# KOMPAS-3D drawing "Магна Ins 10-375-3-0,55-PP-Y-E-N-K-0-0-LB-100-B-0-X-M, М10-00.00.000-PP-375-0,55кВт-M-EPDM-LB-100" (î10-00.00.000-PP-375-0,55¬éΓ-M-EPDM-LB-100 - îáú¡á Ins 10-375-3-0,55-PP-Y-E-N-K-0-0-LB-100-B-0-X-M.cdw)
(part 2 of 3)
- Part/product: Магна Ins 10-425-3-0,75-PP-Y-E-N-K-0-0-L-0-B-0-X-M  | designation М10-00.00.000-PP-425-0,75кВт-M-EPDM
    Масса: 15.988
  - Component [detail]: Заглушка @2~25 FV PPR ф. "FV-Plast"  | qty 4  | pos. 12  | Материал: Полипропилен  ГОСТ 26996-86 (density 900 kg/m3); Масса: 0.0161976; Раздел спецификации: Прочие изделия
  - Component [standard]: Болт М10-6gx60.21.12Х18Н10Т ГОСТ 7798-70  | qty 4  | pos. 8  | Масса: 0.0467; Раздел спецификации: Стандартные изделия; additional columns: М8-6gx55.21.12Х18Н10Т; Сталь 12Х18Н10Т ГОСТ 5632-72
  - Component [standard]: Гайка М10x1,25-6H(S16) ГОСТ 5915-70  | qty 4  | pos. 9  | Масса: 0.01022; Раздел спецификации: Стандартные изделия; Рассекать на разрезах: no; additional columns: М10x1,25-6H (S16); Сталь 12Х18Н10Т ГОСТ 5632-72
  - Component [standard]: Шайба 10 ГОСТ 6402-70  | qty 4  | pos. 10  | Масса: 0.00201; Раздел спецификации: Стандартные изделия; Примечание: Нерж.; Рассекать на разрезах: no; additional columns: 10; Без указания материала
  - Component [standard]: Шайба C.10.21 ГОСТ 11371-78  | qty 4  | pos. 11  | Материал: Сталь 12Х18Н10Т ГОСТ 5632-72 (density 1000 kg/m3); Масса: 0.003438; Раздел спецификации: Стандартные изделия; Рассекать на разрезах: no; additional columns: Сталь 12Х18Н10Т ГОСТ 5632-72
  - Component [standard]: Шайба C.10.21 ГОСТ 11371-78  | qty 4  | pos. 11  | Материал: Сталь 12Х18Н10Т ГОСТ 5632-72 (density 1000 kg/m3); Масса: 0.003438; Раздел спецификации: Стандартные изделия; additional columns: C.8.21; Сталь 12Х18Н10Т ГОСТ 5632-72
  - Component [detail]: Втулка ответная  | designation М10А-00.00.003-01  | pos. 6  | Масса: 0.031838; Раздел спецификации: Детали; Форматы листов документа: A4; Примечание: Заим.; source file: ..\..\..\..\..\..\AquaProf\АкваProf 190\3Д модель\М10А-00.00.003 - Втулка ответная.m3d, ..\М10А-00.00.003-01 - Втулка ответная.cdw
  - Component [detail]: Защитная втулка  | designation М10-00.00.003  | pos. 5  | Масса: 0.0193569; Раздел спецификации: Детали; Форматы листов документа: A4; source file: ..\М10-00.00.003 - Защитная втулка.cdw, ..\М10-00.00.003 - Защитная втулка.m3d
  - Component [detail]: Импеллер Магна10  | designation М10-00.00.001  | pos. 3  | Масса: 0.169927; Раздел спецификации: Детали; Форматы листов документа: A3; source file: ..\М10-00.00.001 - Импеллер Магна10.cdw, ..\М10-00.00.001 - Импеллер Магна10.m3d
  - Component [detail]: Крышка  | designation М10-00.00.002  | pos. 4
      Материал: Полипропилен  ГОСТ 26996-86 (density 900 kg/m3)
      Масса: 0.324102
      Раздел спецификации: Детали
      Форматы листов документа: 4xA4
      Примечание: @100~)4xA4
      source file: ..\М10-00.00.002 - Крышка.cdw, ..\М10-00.00.002 - Крышка.m3d
  - Component [assembly]: Вал  | designation М10-00.15.000-0,75кВт-425  | pos. 1
      Материал: Полипропилен  ГОСТ 26996-86 (density 900 kg/m3)
      Масса: 0.908797
      Раздел спецификации: Сборочные единицы
      Форматы листов документа: 2xA3
      Примечание: @100~)2xA3
      source file: ..\М10-00.15.000 - Вал.a3d
  - Component [assembly]: Корпус полипропилен 425 0,75кВт  / с разъёмной муфтой  | designation М10-00.20.000-PP-425-0,75кВт-M  | pos. 2  | Материал: Полипропилен  ГОСТ 26996-86 (density 900 kg/m3); Масса: 5.90542; Раздел спецификации: Сборочные единицы; Форматы листов документа: 3xA3; Примечание: @100~)3xA3@101~)3xA3
- Part/product: Магна Ins 10-425-3-0,75-PP-Y-E-N-K-0-0-L-0-B-0-X-R  | designation М10-00.00.000-PP-425-0,75кВт-R-EPDM
    Масса: 15.0715
  - Component [detail]: Заглушка @2~25 FV PPR ф. "FV-Plast"  | qty 4  | pos. 12  | Материал: Полипропилен  ГОСТ 26996-86 (density 900 kg/m3); Масса: 0.0161976; Раздел спецификации: Прочие изделия
  - Component [standard]: Болт М10-6gx60.21.12Х18Н10Т ГОСТ 7798-70  | qty 4  | pos. 8  | Масса: 0.0467; Раздел спецификации: Стандартные изделия; additional columns: М8-6gx55.21.12Х18Н10Т; Сталь 12Х18Н10Т ГОСТ 5632-72
  - Component [standard]: Гайка М10x1,25-6H(S16) ГОСТ 5915-70  | qty 4  | pos. 9  | Масса: 0.01022; Раздел спецификации: Стандартные изделия; Рассекать на разрезах: no; additional columns: М10x1,25-6H (S16); Сталь 12Х18Н10Т ГОСТ 5632-72
  - Component [standard]: Шайба 10 ГОСТ 6402-70  | qty 4  | pos. 10  | Масса: 0.00201; Раздел спецификации: Стандартные изделия; Примечание: Нерж.; Рассекать на разрезах: no; additional columns: 10; Без указания материала
  - Component [standard]: Шайба C.10.21 ГОСТ 11371-78  | qty 4  | pos. 11  | Материал: Сталь 12Х18Н10Т ГОСТ 5632-72 (density 1000 kg/m3); Масса: 0.003438; Раздел спецификации: Стандартные изделия; Рассекать на разрезах: no; additional columns: Сталь 12Х18Н10Т ГОСТ 5632-72
  - Component [standard]: Шайба C.10.21 ГОСТ 11371-78  | qty 4  | pos. 11  | Материал: Сталь 12Х18Н10Т ГОСТ 5632-72 (density 1000 kg/m3); Масса: 0.003438; Раздел спецификации: Стандартные изделия; additional columns: C.8.21; Сталь 12Х18Н10Т ГОСТ 5632-72
  - Component [detail]: Втулка ответная  | designation М10А-00.00.003-01  | pos. 6  | Масса: 0.031838; Раздел спецификации: Детали; Форматы листов документа: A4; Примечание: Заим.; source file: ..\..\..\..\..\..\AquaProf\АкваProf 190\3Д модель\М10А-00.00.003 - Втулка ответная.m3d, ..\М10А-00.00.003-01 - Втулка ответная.cdw
  - Component [detail]: Защитная втулка  | designation М10-00.00.003  | pos. 5  | Масса: 0.0193569; Раздел спецификации: Детали; Форматы листов документа: A4; source file: ..\М10-00.00.003 - Защитная втулка.cdw, ..\М10-00.00.003 - Защитная втулка.m3d
  - Component [detail]: Импеллер Магна10  | designation М10-00.00.001  | pos. 3  | Масса: 0.169927; Раздел спецификации: Детали; Форматы листов документа: A3; source file: ..\М10-00.00.001 - Импеллер Магна10.cdw, ..\М10-00.00.001 - Импеллер Магна10.m3d
  - Component [detail]: Крышка  | designation М10-00.00.002  | pos. 4
      Материал: Полипропилен  ГОСТ 26996-86 (density 900 kg/m3)
      Масса: 0.324102
      Раздел спецификации: Детали
      Форматы листов документа: 4xA4
      Примечание: @100~)4xA4
      source file: ..\М10-00.00.002 - Крышка.cdw, ..\М10-00.00.002 - Крышка.m3d
  - Component [assembly]: Вал  | designation М10-00.15.000-0,75кВт-425  | pos. 1
      Материал: Полипропилен  ГОСТ 26996-86 (density 900 kg/m3)
      Масса: 0.908797
      Раздел спецификации: Сборочные единицы
      Форматы листов документа: 2xA3
      Примечание: @100~)2xA3
      source file: ..\М10-00.15.000 - Вал.a3d
  - Component [assembly]: Корпус полипропилен 425 0,75кВт  / с резьбовым переходником  | designation М10-00.20.000-PP-425-0,75кВт-R  | pos. 2  | Материал: Полипропилен  ГОСТ 26996-86 (density 900 kg/m3); Масса: 4.98891; Раздел спецификации: Сборочные единицы; Форматы листов документа: 3xA3; Примечание: @100~)3xA3@101~)3xA3
- Part/product: Магна Ins 10-425-3-1,1-PP-Y-E-N-K-0-0-L-0-B-0-X-M  | designation М10-00.00.000-PP-425-1,1кВт-M-EPDM
    Масса: 15.9855
  - Component [detail]: Заглушка @2~25 FV PPR ф. "FV-Plast"  | qty 4  | pos. 12  | Материал: Полипропилен  ГОСТ 26996-86 (density 900 kg/m3); Масса: 0.0161976; Раздел спецификации: Прочие изделия
  - Component [standard]: Болт М10-6gx60.21.12Х18Н10Т ГОСТ 7798-70  | qty 4  | pos. 8  | Масса: 0.0467; Раздел спецификации: Стандартные изделия; additional columns: М8-6gx55.21.12Х18Н10Т; Сталь 12Х18Н10Т ГОСТ 5632-72
  - Component [standard]: Гайка М10x1,25-6H(S16) ГОСТ 5915-70  | qty 4  | pos. 9  | Масса: 0.01022; Раздел спецификации: Стандартные изделия; Рассекать на разрезах: no; additional columns: М10x1,25-6H (S16); Сталь 12Х18Н10Т ГОСТ 5632-72
  - Component [standard]: Шайба 10 ГОСТ 6402-70  | qty 4  | pos. 10  | Масса: 0.00201; Раздел спецификации: Стандартные изделия; Примечание: Нерж.; Рассекать на разрезах: no; additional columns: 10; Без указания материала
  - Component [standard]: Шайба C.10.21 ГОСТ 11371-78  | qty 4  | pos. 11  | Материал: Сталь 12Х18Н10Т ГОСТ 5632-72 (density 1000 kg/m3); Масса: 0.003438; Раздел спецификации: Стандартные изделия; Рассекать на разрезах: no; additional columns: Сталь 12Х18Н10Т ГОСТ 5632-72
  - Component [standard]: Шайба C.10.21 ГОСТ 11371-78  | qty 4  | pos. 11  | Материал: Сталь 12Х18Н10Т ГОСТ 5632-72 (density 1000 kg/m3); Масса: 0.003438; Раздел спецификации: Стандартные изделия; additional columns: C.8.21; Сталь 12Х18Н10Т ГОСТ 5632-72
  - Component [detail]: Втулка ответная  | designation М10А-00.00.003-01  | pos. 6  | Масса: 0.031838; Раздел спецификации: Детали; Форматы листов документа: A4; Примечание: Заим.; source file: ..\..\..\..\..\..\AquaProf\АкваProf 190\3Д модель\М10А-00.00.003 - Втулка ответная.m3d, ..\М10А-00.00.003-01 - Втулка ответная.cdw
  - Component [detail]: Защитная втулка  | designation М10-00.00.003  | pos. 5  | Масса: 0.0193569; Раздел спецификации: Детали; Форматы листов документа: A4; source file: ..\М10-00.00.003 - Защитная втулка.cdw, ..\М10-00.00.003 - Защитная втулка.m3d
  - Component [detail]: Импеллер Магна10  | designation М10-00.00.001  | pos. 3  | Масса: 0.169927; Раздел спецификации: Детали; Форматы листов документа: A3; source file: ..\М10-00.00.001 - Импеллер Магна10.cdw, ..\М10-00.00.001 - Импеллер Магна10.m3d
  - Component [detail]: Крышка  | designation М10-00.00.002  | pos. 4
      Материал: Полипропилен  ГОСТ 26996-86 (density 900 kg/m3)
      Масса: 0.324102
      Раздел спецификации: Детали
      Форматы листов документа: 4xA4
      Примечание: @100~)4xA4
      source file: ..\М10-00.00.002 - Крышка.cdw, ..\М10-00.00.002 - Крышка.m3d
  - Component [assembly]: Вал  | designation М10-00.15.000-1,1кВт-425  | pos. 1
      Материал: Полипропилен  ГОСТ 26996-86 (density 900 kg/m3)
      Масса: 0.906297
      Раздел спецификации: Сборочные единицы
      Форматы листов документа: 2xA3
      Примечание: @100~)2xA3
      source file: ..\М10-00.15.000 - Вал.a3d
  - Component [detail]: Электродвигатель / АИР 71B2 IM 3081 IP55 ф."Элком"  | pos. 14  | Масса: 8.3; Раздел спецификации: Прочие изделия; Примечание: См. заказ
  - Component [assembly]: Корпус полипропилен 425 1,1кВт  / с разъёмной муфтой  | designation М10-00.20.000-PP-425-1,1кВт-M  | pos. 2  | Материал: Полипропилен  ГОСТ 26996-86 (density 900 kg/m3); Масса: 5.90542; Раздел спецификации: Сборочные единицы; Форматы листов документа: 3xA3; Примечание: @100~)3xA3@101~)3xA3
- Part/product: Магна Ins 10-425-3-1,1-PP-Y-E-N-K-0-0-L-0-B-0-X-R  | designation М10-00.00.000-PP-425-1,1кВт-R-EPDM
    Масса: 15.069
  - Component [detail]: Заглушка @2~25 FV PPR ф. "FV-Plast"  | qty 4  | pos. 12  | Материал: Полипропилен  ГОСТ 26996-86 (density 900 kg/m3); Масса: 0.0161976; Раздел спецификации: Прочие изделия
  - Component [standard]: Болт М10-6gx60.21.12Х18Н10Т ГОСТ 7798-70  | qty 4  | pos. 8  | Масса: 0.0467; Раздел спецификации: Стандартные изделия; additional columns: М8-6gx55.21.12Х18Н10Т; Сталь 12Х18Н10Т ГОСТ 5632-72
  - Component [standard]: Гайка М10x1,25-6H(S16) ГОСТ 5915-70  | qty 4  | pos. 9  | Масса: 0.01022; Раздел спецификации: Стандартные изделия; Рассекать на разрезах: no; additional columns: М10x1,25-6H (S16); Сталь 12Х18Н10Т ГОСТ 5632-72
  - Component [standard]: Шайба 10 ГОСТ 6402-70  | qty 4  | pos. 10  | Масса: 0.00201; Раздел спецификации: Стандартные изделия; Примечание: Нерж.; Рассекать на разрезах: no; additional columns: 10; Без указания материала
  - Component [standard]: Шайба C.10.21 ГОСТ 11371-78  | qty 4  | pos. 11  | Материал: Сталь 12Х18Н10Т ГОСТ 5632-72 (density 1000 kg/m3); Масса: 0.003438; Раздел спецификации: Стандартные изделия; Рассекать на разрезах: no; additional columns: Сталь 12Х18Н10Т ГОСТ 5632-72
  - Component [standard]: Шайба C.10.21 ГОСТ 11371-78  | qty 4  | pos. 11  | Материал: Сталь 12Х18Н10Т ГОСТ 5632-72 (density 1000 kg/m3); Масса: 0.003438; Раздел спецификации: Стандартные изделия; additional columns: C.8.21; Сталь 12Х18Н10Т ГОСТ 5632-72
  - Component [detail]: Втулка ответная  | designation М10А-00.00.003-01  | pos. 6  | Масса: 0.031838; Раздел спецификации: Детали; Форматы листов документа: A4; Примечание: Заим.; source file: ..\..\..\..\..\..\AquaProf\АкваProf 190\3Д модель\М10А-00.00.003 - Втулка ответная.m3d, ..\М10А-00.00.003-01 - Втулка ответная.cdw
  - Component [detail]: Защитная втулка  | designation М10-00.00.003  | pos. 5  | Масса: 0.0193569; Раздел спецификации: Детали; Форматы листов документа: A4; source file: ..\М10-00.00.003 - Защитная втулка.cdw, ..\М10-00.00.003 - Защитная втулка.m3d
  - Component [detail]: Импеллер Магна10  | designation М10-00.00.001  | pos. 3  | Масса: 0.169927; Раздел спецификации: Детали; Форматы листов документа: A3; source file: ..\М10-00.00.001 - Импеллер Магна10.cdw, ..\М10-00.00.001 - Импеллер Магна10.m3d
  - Component [detail]: Крышка  | designation М10-00.00.002  | pos. 4
      Материал: Полипропилен  ГОСТ 26996-86 (density 900 kg/m3)
      Масса: 0.324102
      Раздел спецификации: Детали
      Форматы листов документа: 4xA4
      Примечание: @100~)4xA4
      source file: ..\М10-00.00.002 - Крышка.cdw, ..\М10-00.00.002 - Крышка.m3d
  - Component [assembly]: Вал  | designation М10-00.15.000-1,1кВт-425  | pos. 1
      Материал: Полипропилен  ГОСТ 26996-86 (density 900 kg/m3)
      Масса: 0.906297
      Раздел спецификации: Сборочные единицы
      Форматы листов документа: 2xA3
      Примечание: @100~)2xA3
      source file: ..\М10-00.15.000 - Вал.a3d
  - Component [detail]: Электродвигатель / АИР 71B2 IM 3081 IP55 ф."Элком"  | pos. 14  | Масса: 8.3; Раздел спецификации: Прочие изделия; Примечание: См. заказ
  - Component [assembly]: Корпус полипропилен 425 1,1кВт с резьбовым переходником  | designation М10-00.20.000-PP-425-1,1кВт-R  | pos. 2  | Материал: Полипропилен  ГОСТ 26996-86 (density 900 kg/m3); Масса: 4.98891; Раздел спецификации: Сборочные единицы; Форматы листов документа: 3xA3; Примечание: @100~)3xA3@101~)3xA3
- Part/product: Магна Ins 10-375-3-1,1-PP-Y-E-N-K-0-0-L-0-B-0-X-M  | designation М10-00.00.000-PP-375-1,1кВт-M-EPDM
    Масса: 15.6383
  - Component [detail]: Заглушка @2~25 FV PPR ф. "FV-Plast"  | qty 4  | pos. 12  | Материал: Полипропилен  ГОСТ 26996-86 (density 900 kg/m3); Масса: 0.0161976; Раздел спецификации: Прочие изделия
  - Component [standard]: Болт М10x1,25-6gx60 (S16) ГОСТ 7798-70  | qty 4  | pos. 8  | Масса: 0.0467; Раздел спецификации: Стандартные изделия; Рассекать на разрезах: no; additional columns: Сталь 12Х18Н10Т ГОСТ 5632-72
  - Component [standard]: Гайка М10-6H.21.12Х18Н10Т ГОСТ 5915-70  | qty 4  | pos. 9  | Масса: 0.01022; Раздел спецификации: Стандартные изделия; additional columns: М8-6H.21.12Х18Н10Т; Сталь 12Х18Н10Т ГОСТ 5632-72
  - Component [standard]: Шайба 10 ГОСТ 6402-70  | qty 4  | pos. 10  | Масса: 0.00201; Раздел спецификации: Стандартные изделия; Примечание: Нерж.; additional columns: 8; Без указания материала
  - Component [standard]: Шайба C.10.21 ГОСТ 11371-78  | qty 4  | pos. 11  | Материал: Сталь 12Х18Н10Т ГОСТ 5632-72 (density 1000 kg/m3); Масса: 0.003438; Раздел спецификации: Стандартные изделия; Рассекать на разрезах: no; additional columns: Сталь 12Х18Н10Т ГОСТ 5632-72
  - Component [detail]: Втулка ответная  | designation М10А-00.00.003-01  | pos. 6  | Масса: 0.031838; Раздел спецификации: Детали; Форматы листов документа: A4; Примечание: Заим.; source file: ..\..\..\..\..\..\AquaProf\АкваProf 190\3Д модель\М10А-00.00.003 - Втулка ответная.m3d, ..\М10А-00.00.003-01 - Втулка ответная.cdw
  - Component [detail]: Защитная втулка  | designation М10-00.00.003  | pos. 5  | Масса: 0.0193569; Раздел спецификации: Детали; Форматы листов документа: A4; source file: ..\М10-00.00.003 - Защитная втулка.cdw, ..\М10-00.00.003 - Защитная втулка.m3d
  - Component [detail]: Импеллер Магна10  | designation М10-00.00.001  | pos. 3  | Масса: 0.169927; Раздел спецификации: Детали; Форматы листов документа: A3; source file: ..\М10-00.00.001 - Импеллер Магна10.cdw, ..\М10-00.00.001 - Импеллер Магна10.m3d
  - Component [detail]: Крышка  | designation М10-00.00.002  | pos. 4
      Материал: Полипропилен  ГОСТ 26996-86 (density 900 kg/m3)
      Масса: 0.324102
      Раздел спецификации: Детали
      Форматы листов документа: 4xA4
      Примечание: @100~)4xA4
      source file: ..\М10-00.00.002 - Крышка.cdw, ..\М10-00.00.002 - Крышка.m3d
  - Component [assembly]: Вал  | designation М10-00.15.000-1,1кВт-375  | pos. 1
      Материал: Полипропилен  ГОСТ 26996-86 (density 900 kg/m3)
      Масса: 0.865208
      Раздел спецификации: Сборочные единицы
      Форматы листов документа: 2xA3
      Примечание: @100~)2xA3
      source file: ..\М10-00.15.000 - Вал.a3d
  - Component [detail]: Электродвигатель / АИР 71B2 IM 3081 IP55 ф."Элком"  | pos. 14  | Масса: 8.3; Раздел спецификации: Прочие изделия; Примечание: См. заказ
  - Component [assembly]: Корпус полипропилен 375 1,1кВт  / с разъёмной муфтой  | designation М10-00.20.000-PP-375-1,1кВт-M  | pos. 2  | Материал: Полипропилен  ГОСТ 26996-86 (density 900 kg/m3); Масса: 5.65999; Раздел спецификации: Сборочные единицы; Форматы листов документа: 3xA3; Примечание: @100~)3xA3@101~)3xA3
- Part/product: Магна Ins 10-375-3-1,1-PP-Y-E-N-K-0-0-L-0-B-0-X-R  | designation М10-00.00.000-PP-375-1,1кВт-R-EPDM
    Масса: 14.7218
  - Component [detail]: Заглушка @2~25 FV PPR ф. "FV-Plast"  | qty 4  | pos. 12  | Материал: Полипропилен  ГОСТ 26996-86 (density 900 kg/m3); Масса: 0.0161976; Раздел спецификации: Прочие изделия
  - Component [standard]: Болт М10x1,25-6gx60 (S16) ГОСТ 7798-70  | qty 4  | pos. 8  | Масса: 0.0467; Раздел спецификации: Стандартные изделия; Рассекать на разрезах: no; additional columns: Сталь 12Х18Н10Т ГОСТ 5632-72
  - Component [standard]: Гайка М10-6H.21.12Х18Н10Т ГОСТ 5915-70  | qty 4  | pos. 9  | Масса: 0.01022; Раздел спецификации: Стандартные изделия; additional columns: М8-6H.21.12Х18Н10Т; Сталь 12Х18Н10Т ГОСТ 5632-72
  - Component [standard]: Шайба 10 ГОСТ 6402-70  | qty 4  | pos. 10  | Масса: 0.00201; Раздел спецификации: Стандартные изделия; Примечание: Нерж.; additional columns: 8; Без указания материала
  - Component [standard]: Шайба C.10.21 ГОСТ 11371-78  | qty 4  | pos. 11  | Материал: Сталь 12Х18Н10Т ГОСТ 5632-72 (density 1000 kg/m3); Масса: 0.003438; Раздел спецификации: Стандартные изделия; Рассекать на разрезах: no; additional columns: Сталь 12Х18Н10Т ГОСТ 5632-72
  - Component [standard]: Шайба C.10.21 ГОСТ 11371-78  | qty 4  | pos. 11  | Материал: Сталь 12Х18Н10Т ГОСТ 5632-72 (density 1000 kg/m3); Масса: 0.003438; Раздел спецификации: Стандартные изделия; additional columns: C.8.21; Сталь 12Х18Н10Т ГОСТ 5632-72
  - Component [detail]: Втулка ответная  | designation М10А-00.00.003-01  | pos. 6  | Масса: 0.031838; Раздел спецификации: Детали; Форматы листов документа: A4; Примечание: Заим.; source file: ..\..\..\..\..\..\AquaProf\АкваProf 190\3Д модель\М10А-00.00.003 - Втулка ответная.m3d, ..\М10А-00.00.003-01 - Втулка ответная.cdw
  - Component [detail]: Защитная втулка  | designation М10-00.00.003  | pos. 5  | Масса: 0.0193569; Раздел спецификации: Детали; Форматы листов документа: A4; source file: ..\М10-00.00.003 - Защитная втулка.cdw, ..\М10-00.00.003 - Защитная втулка.m3d
  - Component [detail]: Импеллер Магна10  | designation М10-00.00.001  | pos. 3  | Масса: 0.169927; Раздел спецификации: Детали; Форматы листов документа: A3; source file: ..\М10-00.00.001 - Импеллер Магна10.cdw, ..\М10-00.00.001 - Импеллер Магна10.m3d
  - Component [detail]: Крышка  | designation М10-00.00.002  | pos. 4
      Материал: Полипропилен  ГОСТ 26996-86 (density 900 kg/m3)
      Масса: 0.324102
      Раздел спецификации: Детали
      Форматы листов документа: 4xA4
      Примечание: @100~)4xA4
      source file: ..\М10-00.00.002 - Крышка.cdw, ..\М10-00.00.002 - Крышка.m3d
  - Component [assembly]: Вал  | designation М10-00.15.000-1,1кВт-375  | pos. 1
      Материал: Полипропилен  ГОСТ 26996-86 (density 900 kg/m3)
      Масса: 0.865208
      Раздел спецификации: Сборочные единицы
      Форматы листов документа: 2xA3
      Примечание: @100~)2xA3
      source file: ..\М10-00.15.000 - Вал.a3d
  - Component [detail]: Электродвигатель / АИР 71B2 IM 3081 IP55 ф."Элком"  | pos. 14  | Масса: 8.3; Раздел спецификации: Прочие изделия; Примечание: См. заказ
  - Component [assembly]: Корпус полипропилен 375 1,1кВт  / с резьбовым переходником  | designation М10-00.20.000-PP-375-1,1кВт-R  | pos. 2  | Материал: Полипропилен  ГОСТ 26996-86 (density 900 kg/m3); Масса: 4.74348; Раздел спецификации: Сборочные единицы; Форматы листов документа: 3xA3; Примечание: @100~)3xA3@101~)3xA3
- Part/product: Магна Ins 10-PP-475-0,55кВт  | designation М10-00.00.000-PP-475-0,55кВт
    Масса: 11.8893
  - Component [assembly]: Корпус полипропилен  | designation М10-00.20.000-PP-475  | pos. 2  | Материал: Полипропилен  ГОСТ 26996-86 (density 900 kg/m3); Масса: 5.45783; Раздел спецификации: Сборочные единицы; Форматы листов документа: 3xA3; Примечание: @100~)3xA3@101~)3xA3
  - Component [assembly]: Вал  | designation М10-00.15.000-0,55кВт-475  | pos. 1
      Материал: Полипропилен  ГОСТ 26996-86 (density 900 kg/m3)
      Масса: 0.642468
      Раздел спецификации: Сборочные единицы
      Форматы листов документа: 2xA3
      Примечание: @100~)2xA3
      source file: ..\М10-00.15.000 - Вал.a3d
  - Component [detail]: Крышка  | designation М10-00.00.002  | pos. 4
      Материал: Полипропилен  ГОСТ 26996-86 (density 900 kg/m3)
      Масса: 0.324102
      Раздел спецификации: Детали
      Форматы листов документа: 4xA4
      Примечание: @100~)4xA4
      source file: ..\М10-00.00.002 - Крышка.cdw, ..\М10-00.00.002 - Крышка.m3d
  - Component [detail]: Импеллер Магна10  | designation М10-00.00.001  | pos. 3  | Масса: 0.169927; Раздел спецификации: Детали; Форматы листов документа: A3; source file: ..\М10-00.00.001 - Импеллер Магна10.cdw, ..\М10-00.00.001 - Импеллер Магна10.m3d
  - Component [detail]: Защитная втулка  | designation М10-00.00.003  | pos. 5  | Масса: 0.0193569; Раздел спецификации: Детали; Форматы листов документа: A4; source file: ..\М10-00.00.003 - Защитная втулка.cdw, ..\М10-00.00.003 - Защитная втулка.m3d
  - Component [detail]: Втулка ответная  | designation М10А-00.00.003-01  | pos. 6  | Масса: 0.031838; Раздел спецификации: Детали; Форматы листов документа: A4; Примечание: Заим.; source file: ..\..\..\..\..\..\AquaProf\АкваProf 190\3Д модель\М10А-00.00.003 - Втулка ответная.m3d, ..\М10А-00.00.003-01 - Втулка ответная.cdw
- Part/product: Магна Ins 10-PP-475-0,75кВт  | designation М10-00.00.000-PP-475-0,75кВт
    Масса: 15.3858
  - Component [assembly]: Корпус полипропилен 475 0,75кВт  | designation М10-00.20.000-PP-475-0,75кВт  | pos. 2  | Материал: Полипропилен  ГОСТ 26996-86 (density 900 kg/m3); Масса: 5.20146; Раздел спецификации: Сборочные единицы; Форматы листов документа: 3xA3; Примечание: @100~)3xA3@101~)3xA3
  - Component [assembly]: Вал  | designation М10-00.15.000-0,75кВт-475  | pos. 1
      Материал: Полипропилен  ГОСТ 26996-86 (density 900 kg/m3)
      Масса: 1.01058
      Раздел спецификации: Сборочные единицы
      Форматы листов документа: 2xA3
      Примечание: @100~)2xA3
      source file: ..\М10-00.15.000 - Вал.a3d
  - Component [detail]: Крышка  | designation М10-00.00.002  | pos. 4
      Материал: Полипропилен  ГОСТ 26996-86 (density 900 kg/m3)
      Масса: 0.324102
      Раздел спецификации: Детали
      Форматы листов документа: 4xA4
      Примечание: @100~)4xA4
      source file: ..\М10-00.00.002 - Крышка.cdw, ..\М10-00.00.002 - Крышка.m3d
  - Component [detail]: Импеллер Магна10  | designation М10-00.00.001  | pos. 3  | Масса: 0.169927; Раздел спецификации: Детали; Форматы листов документа: A3; source file: ..\М10-00.00.001 - Импеллер Магна10.cdw, ..\М10-00.00.001 - Импеллер Магна10.m3d
  - Component [detail]: Защитная втулка  | designation М10-00.00.003  | pos. 5  | Масса: 0.0193569; Раздел спецификации: Детали; Форматы листов документа: A4; source file: ..\М10-00.00.003 - Защитная втулка.cdw, ..\М10-00.00.003 - Защитная втулка.m3d
  - Component [detail]: Втулка ответная  | designation М10А-00.00.003-01  | pos. 6  | Масса: 0.031838; Раздел спецификации: Детали; Форматы листов документа: A4; Примечание: Заим.; source file: ..\..\..\..\..\..\AquaProf\АкваProf 190\3Д модель\М10А-00.00.003 - Втулка ответная.m3d, ..\М10А-00.00.003-01 - Втулка ответная.cdw
  - Component [standard]: Шайба C.10.21 ГОСТ 11371-78  | qty 8  | pos. 11  | Материал: Сталь 12Х18Н10Т ГОСТ 5632-72 (density 1000 kg/m3); Масса: 0.003438; Раздел спецификации: Стандартные изделия; Рассекать на разрезах: no; additional columns: Сталь 12Х18Н10Т ГОСТ 5632-72
  - Component [standard]: Шайба 10 ГОСТ 6402-70  | qty 4  | pos. 10  | Масса: 0.00201; Раздел спецификации: Стандартные изделия; Примечание: Нерж.; Рассекать на разрезах: no; additional columns: 10; Без указания материала
  - Component [standard]: Гайка М10x1,25-6H(S16) ГОСТ 5915-70  | qty 4  | pos. 9  | Масса: 0.01022; Раздел спецификации: Стандартные изделия; Рассекать на разрезах: no; additional columns: М10x1,25-6H (S16); Сталь 12Х18Н10Т ГОСТ 5632-72
  - Component [standard]: Болт М10x1,25-6gx60 (S16) ГОСТ 7798-70  | qty 4  | pos. 8  | Масса: 0.0467; Раздел спецификации: Стандартные изделия; Рассекать на разрезах: no; additional columns: Сталь 12Х18Н10Т ГОСТ 5632-72
  - Component [detail]: Заглушка @2~25 FV PPR ф. "FV-Plast"  | qty 4  | pos. 12  | Материал: Полипропилен  ГОСТ 26996-86 (density 900 kg/m3); Масса: 0.0161976; Раздел спецификации: Прочие изделия
- Part/product: Магна Ins 10-PP-475-1,1кВт  | designation М10-00.00.000-PP-475-1,1кВт
    Масса: 15.3833
  - Component [assembly]: Корпус полипропилен 475 1,1кВт  | designation М10-00.20.000-PP-475-1,1кВт  | pos. 2  | Материал: Полипропилен  ГОСТ 26996-86 (density 900 kg/m3); Масса: 5.20146; Раздел спецификации: Сборочные единицы; Форматы листов документа: 3xA3; Примечание: @100~)3xA3@101~)3xA3
  - Component [detail]: Электродвигатель / АИР 71B2 IM 3081 IP55 ф."Элком"  | pos. 14  | Масса: 8.3; Раздел спецификации: Прочие изделия; Примечание: См. заказ
  - Component [assembly]: Вал  | designation М10-00.15.000-1,1кВт-475  | pos. 1
      Материал: Полипропилен  ГОСТ 26996-86 (density 900 kg/m3)
      Масса: 1.00808
      Раздел спецификации: Сборочные единицы
      Форматы листов документа: 2xA3
      Примечание: @100~)2xA3
      source file: ..\М10-00.15.000 - Вал.a3d
  - Component [detail]: Крышка  | designation М10-00.00.002  | pos. 4
      Материал: Полипропилен  ГОСТ 26996-86 (density 900 kg/m3)
      Масса: 0.324102
      Раздел спецификации: Детали
      Форматы листов документа: 4xA4
      Примечание: @100~)4xA4
      source file: ..\М10-00.00.002 - Крышка.cdw, ..\М10-00.00.002 - Крышка.m3d
  - Component [detail]: Импеллер Магна10  | designation М10-00.00.001  | pos. 3  | Масса: 0.169927; Раздел спецификации: Детали; Форматы листов документа: A3; source file: ..\М10-00.00.001 - Импеллер Магна10.cdw, ..\М10-00.00.001 - Импеллер Магна10.m3d
  - Component [detail]: Защитная втулка  | designation М10-00.00.003  | pos. 5  | Масса: 0.0193569; Раздел спецификации: Детали; Форматы листов документа: A4; source file: ..\М10-00.00.003 - Защитная втулка.cdw, ..\М10-00.00.003 - Защитная втулка.m3d
  - Component [detail]: Втулка ответная  | designation М10А-00.00.003-01  | pos. 6  | Масса: 0.031838; Раздел спецификации: Детали; Форматы листов документа: A4; Примечание: Заим.; source file: ..\..\..\..\..\..\AquaProf\АкваProf 190\3Д модель\М10А-00.00.003 - Втулка ответная.m3d, ..\М10А-00.00.003-01 - Втулка ответная.cdw
  - Component [standard]: Шайба C.10.21 ГОСТ 11371-78  | qty 8  | pos. 11  | Материал: Сталь 12Х18Н10Т ГОСТ 5632-72 (density 1000 kg/m3); Масса: 0.003438; Раздел спецификации: Стандартные изделия; Рассекать на разрезах: no; additional columns: Сталь 12Х18Н10Т ГОСТ 5632-72
  - Component [standard]: Шайба 10 ГОСТ 6402-70  | qty 4  | pos. 10  | Масса: 0.00201; Раздел спецификации: Стандартные изделия; Примечание: Нерж.; Рассекать на разрезах: no; additional columns: 10; Без указания материала
  - Component [standard]: Гайка М10x1,25-6H(S16) ГОСТ 5915-70  | qty 4  | pos. 9  | Масса: 0.01022; Раздел спецификации: Стандартные изделия; Рассекать на разрезах: no; additional columns: М10x1,25-6H (S16); Сталь 12Х18Н10Т ГОСТ 5632-72
  - Component [standard]: Болт М10x1,25-6gx60 (S16) ГОСТ 7798-70  | qty 4  | pos. 8  | Масса: 0.0467; Раздел спецификации: Стандартные изделия; Рассекать на разрезах: no; additional columns: Сталь 12Х18Н10Т ГОСТ 5632-72
  - Component [detail]: Заглушка @2~25 FV PPR ф. "FV-Plast"  | qty 4  | pos. 12  | Материал: Полипропилен  ГОСТ 26996-86 (density 900 kg/m3); Масса: 0.0161976; Раздел спецификации: Прочие изделия
- Part/product: Магна Ins 10-475-3-0,55-PP-Y-E-N-K-0-0-L-0-B-0-X-M  | designation М10-00.00.000-PP-475-0,55кВт-M
    Масса: 12.8387
  - Component [detail]: Втулка ответная  | designation М10А-00.00.003-01  | pos. 6  | Масса: 0.031838; Раздел спецификации: Детали; Форматы листов документа: A4; Примечание: Заим.; source file: ..\..\..\..\..\..\AquaProf\АкваProf 190\3Д модель\М10А-00.00.003 - Втулка ответная.m3d, ..\М10А-00.00.003-01 - Втулка ответная.cdw
  - Component [detail]: Защитная втулка  | designation М10-00.00.003  | pos. 5  | Масса: 0.0193569; Раздел спецификации: Детали; Форматы листов документа: A4; source file: ..\М10-00.00.003 - Защитная втулка.cdw, ..\М10-00.00.003 - Защитная втулка.m3d
  - Component [detail]: Импеллер Магна10  | designation М10-00.00.001  | pos. 3  | Масса: 0.169927; Раздел спецификации: Детали; Форматы листов документа: A3; source file: ..\М10-00.00.001 - Импеллер Магна10.cdw, ..\М10-00.00.001 - Импеллер Магна10.m3d
  - Component [detail]: Крышка  | designation М10-00.00.002  | pos. 4
      Материал: Полипропилен  ГОСТ 26996-86 (density 900 kg/m3)
      Масса: 0.324102
      Раздел спецификации: Детали
      Форматы листов документа: 4xA4
      Примечание: @100~)4xA4
      source file: ..\М10-00.00.002 - Крышка.cdw, ..\М10-00.00.002 - Крышка.m3d
  - Component [assembly]: Вал  | designation М10-00.15.000-0,55кВт-475  | pos. 1
      Материал: Полипропилен  ГОСТ 26996-86 (density 900 kg/m3)
      Масса: 0.642468
      Раздел спецификации: Сборочные единицы
      Форматы листов документа: 2xA3
      Примечание: @100~)2xA3
      source file: ..\М10-00.15.000 - Вал.a3d
  - Component [assembly]: Корпус полипропилен 475 0,55кВт  / с разъёмной муфтой  | designation М10-00.20.000-PP-475-0,55кВт-M  | pos. 2  | Материал: Полипропилен  ГОСТ 26996-86 (density 900 kg/m3); Масса: 6.40722; Раздел спецификации: Сборочные единицы; Форматы листов документа: 3xA3; Примечание: @100~)3xA3@101~)3xA3
- Part/product: Магна Ins 10-475-3-0,55-PP-Y-E-N-K-0-0-L-0-B-0-X-R  | designation М10-00.00.000-PP-475-0,55кВт-R
    Масса: 11.9222
  - Component [detail]: Втулка ответная  | designation М10А-00.00.003-01  | pos. 6  | Масса: 0.031838; Раздел спецификации: Детали; Форматы листов документа: A4; Примечание: Заим.; source file: ..\..\..\..\..\..\AquaProf\АкваProf 190\3Д модель\М10А-00.00.003 - Втулка ответная.m3d, ..\М10А-00.00.003-01 - Втулка ответная.cdw
  - Component [detail]: Защитная втулка  | designation М10-00.00.003  | pos. 5  | Масса: 0.0193569; Раздел спецификации: Детали; Форматы листов документа: A4; source file: ..\М10-00.00.003 - Защитная втулка.cdw, ..\М10-00.00.003 - Защитная втулка.m3d
  - Component [detail]: Импеллер Магна10  | designation М10-00.00.001  | pos. 3  | Масса: 0.169927; Раздел спецификации: Детали; Форматы листов документа: A3; source file: ..\М10-00.00.001 - Импеллер Магна10.cdw, ..\М10-00.00.001 - Импеллер Магна10.m3d
  - Component [detail]: Крышка  | designation М10-00.00.002  | pos. 4
      Материал: Полипропилен  ГОСТ 26996-86 (density 900 kg/m3)
      Масса: 0.324102
      Раздел спецификации: Детали
      Форматы листов документа: 4xA4
      Примечание: @100~)4xA4
      source file: ..\М10-00.00.002 - Крышка.cdw, ..\М10-00.00.002 - Крышка.m3d
  - Component [assembly]: Вал  | designation М10-00.15.000-0,55кВт-475  | pos. 1
      Материал: Полипропилен  ГОСТ 26996-86 (density 900 kg/m3)
      Масса: 0.642468
      Раздел спецификации: Сборочные единицы
      Форматы листов документа: 2xA3
      Примечание: @100~)2xA3
      source file: ..\М10-00.15.000 - Вал.a3d
  - Component [assembly]: Корпус полипропилен 475 0,55кВт  / с резьбовым переходником  | designation М10-00.20.000-PP-475-0,55кВт-R  | pos. 2  | Материал: Полипропилен  ГОСТ 26996-86 (density 900 kg/m3); Масса: 5.49071; Раздел спецификации: Сборочные единицы; Форматы листов документа: 3xA3; Примечание: @100~)3xA3@101~)3xA3
- Part/product: Магна Ins 10-475-3-0,75-PP-Y-E-N-K-0-0-L-0-B-0-X-M  | designation М10-00.00.000-PP-475-0,75кВт-M
    Масса: 16.3352
  - Component [detail]: Заглушка @2~25 FV PPR ф. "FV-Plast"  | qty 4  | pos. 12  | Материал: Полипропилен  ГОСТ 26996-86 (density 900 kg/m3); Масса: 0.0161976; Раздел спецификации: Прочие изделия
  - Component [standard]: Болт М8-6gx60.21.12Х18Н10Т ГОСТ 7798-70  | qty 4  | pos. 8  | Масса: 0.0467; Раздел спецификации: Стандартные изделия; additional columns: М8-6gx55.21.12Х18Н10Т; Сталь 12Х18Н10Т ГОСТ 5632-72
  - Component [standard]: Гайка М10x1,25-6H(S16) ГОСТ 5915-70  | qty 4  | pos. 9  | Масса: 0.01022; Раздел спецификации: Стандартные изделия; Рассекать на разрезах: no; additional columns: М10x1,25-6H (S16); Сталь 12Х18Н10Т ГОСТ 5632-72
  - Component [standard]: Шайба 10 ГОСТ 6402-70  | qty 4  | pos. 10  | Масса: 0.00201; Раздел спецификации: Стандартные изделия; Примечание: Нерж.; Рассекать на разрезах: no; additional columns: 10; Без указания материала
  - Component [standard]: Шайба C.10.21 ГОСТ 11371-78  | qty 4  | pos. 11  | Материал: Сталь 12Х18Н10Т ГОСТ 5632-72 (density 1000 kg/m3); Масса: 0.003438; Раздел спецификации: Стандартные изделия; Рассекать на разрезах: no; additional columns: Сталь 12Х18Н10Т ГОСТ 5632-72
  - Component [standard]: Шайба C.10.21 ГОСТ 11371-78  | qty 4  | pos. 11  | Материал: Сталь 12Х18Н10Т ГОСТ 5632-72 (density 1000 kg/m3); Масса: 0.003438; Раздел спецификации: Стандартные изделия; additional columns: C.8.21; Сталь 12Х18Н10Т ГОСТ 5632-72
  - Component [detail]: Втулка ответная  | designation М10А-00.00.003-01  | pos. 6  | Масса: 0.031838; Раздел спецификации: Детали; Форматы листов документа: A4; Примечание: Заим.; source file: ..\..\..\..\..\..\AquaProf\АкваProf 190\3Д модель\М10А-00.00.003 - Втулка ответная.m3d, ..\М10А-00.00.003-01 - Втулка ответная.cdw
  - Component [detail]: Защитная втулка  | designation М10-00.00.003  | pos. 5  | Масса: 0.0193569; Раздел спецификации: Детали; Форматы листов документа: A4; source file: ..\М10-00.00.003 - Защитная втулка.cdw, ..\М10-00.00.003 - Защитная втулка.m3d
  - Component [detail]: Импеллер Магна10  | designation М10-00.00.001  | pos. 3  | Масса: 0.169927; Раздел спецификации: Детали; Форматы листов документа: A3; source file: ..\М10-00.00.001 - Импеллер Магна10.cdw, ..\М10-00.00.001 - Импеллер Магна10.m3d
  - Component [detail]: Крышка  | designation М10-00.00.002  | pos. 4
      Материал: Полипропилен  ГОСТ 26996-86 (density 900 kg/m3)
      Масса: 0.324102
      Раздел спецификации: Детали
      Форматы листов документа: 4xA4
      Примечание: @100~)4xA4
      source file: ..\М10-00.00.002 - Крышка.cdw, ..\М10-00.00.002 - Крышка.m3d
  - Component [assembly]: Вал  | designation М10-00.15.000-0,75кВт-475  | pos. 1
      Материал: Полипропилен  ГОСТ 26996-86 (density 900 kg/m3)
      Масса: 1.01058
      Раздел спецификации: Сборочные единицы
      Форматы листов документа: 2xA3
      Примечание: @100~)2xA3
      source file: ..\М10-00.15.000 - Вал.a3d
  - Component [assembly]: Корпус полипропилен 475 0,75кВт  / с разъёмной муфтой  | designation М10-00.20.000-PP-475-0,75кВт-M  | pos. 2  | Материал: Полипропилен  ГОСТ 26996-86 (density 900 kg/m3); Масса: 6.15084; Раздел спецификации: Сборочные единицы; Форматы листов документа: 3xA3; Примечание: @100~)3xA3@101~)3xA3
- Part/product: Магна Ins 10-475-3-0,55-PP-Y-E-N-K-0-0-L-0-B-0-X-R  | designation М10-00.00.000-PP-475-0,75кВт-R
    Масса: 15.4187
  - Component [detail]: Заглушка @2~25 FV PPR ф. "FV-Plast"  | qty 4  | pos. 12  | Материал: Полипропилен  ГОСТ 26996-86 (density 900 kg/m3); Масса: 0.0161976; Раздел спецификации: Прочие изделия
  - Component [standard]: Болт М8-6gx60.21.12Х18Н10Т ГОСТ 7798-70  | qty 4  | pos. 8  | Масса: 0.0467; Раздел спецификации: Стандартные изделия; additional columns: М8-6gx55.21.12Х18Н10Т; Сталь 12Х18Н10Т ГОСТ 5632-72
  - Component [standard]: Гайка М10x1,25-6H(S16) ГОСТ 5915-70  | qty 4  | pos. 9  | Масса: 0.01022; Раздел спецификации: Стандартные изделия; Рассекать на разрезах: no; additional columns: М10x1,25-6H (S16); Сталь 12Х18Н10Т ГОСТ 5632-72
  - Component [standard]: Шайба 10 ГОСТ 6402-70  | qty 4  | pos. 10  | Масса: 0.00201; Раздел спецификации: Стандартные изделия; Примечание: Нерж.; Рассекать на разрезах: no; additional columns: 10; Без указания материала
  - Component [standard]: Шайба C.10.21 ГОСТ 11371-78  | qty 4  | pos. 11  | Материал: Сталь 12Х18Н10Т ГОСТ 5632-72 (density 1000 kg/m3); Масса: 0.003438; Раздел спецификации: Стандартные изделия; Рассекать на разрезах: no; additional columns: Сталь 12Х18Н10Т ГОСТ 5632-72
  - Component [standard]: Шайба C.10.21 ГОСТ 11371-78  | qty 4  | pos. 11  | Материал: Сталь 12Х18Н10Т ГОСТ 5632-72 (density 1000 kg/m3); Масса: 0.003438; Раздел спецификации: Стандартные изделия; additional columns: C.8.21; Сталь 12Х18Н10Т ГОСТ 5632-72
  - Component [detail]: Втулка ответная  | designation М10А-00.00.003-01  | pos. 6  | Масса: 0.031838; Раздел спецификации: Детали; Форматы листов документа: A4; Примечание: Заим.; source file: ..\..\..\..\..\..\AquaProf\АкваProf 190\3Д модель\М10А-00.00.003 - Втулка ответная.m3d, ..\М10А-00.00.003-01 - Втулка ответная.cdw
  - Component [detail]: Защитная втулка  | designation М10-00.00.003  | pos. 5  | Масса: 0.0193569; Раздел спецификации: Детали; Форматы листов документа: A4; source file: ..\М10-00.00.003 - Защитная втулка.cdw, ..\М10-00.00.003 - Защитная втулка.m3d
  - Component [detail]: Импеллер Магна10  | designation М10-00.00.001  | pos. 3  | Масса: 0.169927; Раздел спецификации: Детали; Форматы листов документа: A3; source file: ..\М10-00.00.001 - Импеллер Магна10.cdw, ..\М10-00.00.001 - Импеллер Магна10.m3d
  - Component [detail]: Крышка  | designation М10-00.00.002  | pos. 4
      Материал: Полипропилен  ГОСТ 26996-86 (density 900 kg/m3)
      Масса: 0.324102
      Раздел спецификации: Детали
      Форматы листов документа: 4xA4
      Примечание: @100~)4xA4
      source file: ..\М10-00.00.002 - Крышка.cdw, ..\М10-00.00.002 - Крышка.m3d
  - Component [assembly]: Вал  | designation М10-00.15.000-0,75кВт-475  | pos. 1
      Материал: Полипропилен  ГОСТ 26996-86 (density 900 kg/m3)
      Масса: 1.01058
      Раздел спецификации: Сборочные единицы
      Форматы листов документа: 2xA3
      Примечание: @100~)2xA3
      source file: ..\М10-00.15.000 - Вал.a3d
  - Component [assembly]: Корпус полипропилен 475 0,75кВт м резьбовым переходником  | designation М10-00.20.000-PP-475-0,75кВт-R  | pos. 2  | Материал: Полипропилен  ГОСТ 26996-86 (density 900 kg/m3); Масса: 5.23433; Раздел спецификации: Сборочные единицы; Форматы листов документа: 3xA3; Примечание: @100~)3xA3@101~)3xA3
- Part/product: Магна Ins 10-475-3-1,1-PP-Y-E-N-K-0-0-L-0-B-0-X-M  | designation М10-00.00.000-PP-475-1,1кВт-M
    Масса: 16.3327
  - Component [detail]: Заглушка @2~25 FV PPR ф. "FV-Plast"  | qty 4  | pos. 12  | Материал: Полипропилен  ГОСТ 26996-86 (density 900 kg/m3); Масса: 0.0161976; Раздел спецификации: Прочие изделия
  - Component [standard]: Болт М10-6gx60.21.12Х18Н10Т ГОСТ 7798-70  | qty 4  | pos. 8  | Масса: 0.0467; Раздел спецификации: Стандартные изделия; additional columns: М8-6gx55.21.12Х18Н10Т; Сталь 12Х18Н10Т ГОСТ 5632-72
  - Component [standard]: Гайка М10x1,25-6H(S16) ГОСТ 5915-70  | qty 4  | pos. 9  | Масса: 0.01022; Раздел спецификации: Стандартные изделия; Рассекать на разрезах: no; additional columns: М10x1,25-6H (S16); Сталь 12Х18Н10Т ГОСТ 5632-72
  - Component [standard]: Шайба 10 ГОСТ 6402-70  | qty 4  | pos. 10  | Масса: 0.00201; Раздел спецификации: Стандартные изделия; Примечание: Нерж.; Рассекать на разрезах: no; additional columns: 10; Без указания материала
  - Component [standard]: Шайба C.10.21 ГОСТ 11371-78  | qty 4  | pos. 11  | Материал: Сталь 12Х18Н10Т ГОСТ 5632-72 (density 1000 kg/m3); Масса: 0.003438; Раздел спецификации: Стандартные изделия; Рассекать на разрезах: no; additional columns: Сталь 12Х18Н10Т ГОСТ 5632-72
  - Component [standard]: Шайба C.10.21 ГОСТ 11371-78  | qty 4  | pos. 11  | Материал: Сталь 12Х18Н10Т ГОСТ 5632-72 (density 1000 kg/m3); Масса: 0.003438; Раздел спецификации: Стандартные изделия; additional columns: C.8.21; Сталь 12Х18Н10Т ГОСТ 5632-72
  - Component [detail]: Втулка ответная  | designation М10А-00.00.003-01  | pos. 6  | Масса: 0.031838; Раздел спецификации: Детали; Форматы листов документа: A4; Примечание: Заим.; source file: ..\..\..\..\..\..\AquaProf\АкваProf 190\3Д модель\М10А-00.00.003 - Втулка ответная.m3d, ..\М10А-00.00.003-01 - Втулка ответная.cdw
  - Component [detail]: Защитная втулка  | designation М10-00.00.003  | pos. 5  | Масса: 0.0193569; Раздел спецификации: Детали; Форматы листов документа: A4; source file: ..\М10-00.00.003 - Защитная втулка.cdw, ..\М10-00.00.003 - Защитная втулка.m3d
  - Component [detail]: Импеллер Магна10  | designation М10-00.00.001  | pos. 3  | Масса: 0.169927; Раздел спецификации: Детали; Форматы листов документа: A3; source file: ..\М10-00.00.001 - Импеллер Магна10.cdw, ..\М10-00.00.001 - Импеллер Магна10.m3d
  - Component [detail]: Крышка  | designation М10-00.00.002  | pos. 4
      Материал: Полипропилен  ГОСТ 26996-86 (density 900 kg/m3)
      Масса: 0.324102
      Раздел спецификации: Детали
      Форматы листов документа: 4xA4
      Примечание: @100~)4xA4
      source file: ..\М10-00.00.002 - Крышка.cdw, ..\М10-00.00.002 - Крышка.m3d
  - Component [assembly]: Вал  | designation М10-00.15.000-1,1кВт-475  | pos. 1
      Материал: Полипропилен  ГОСТ 26996-86 (density 900 kg/m3)
      Масса: 1.00808
      Раздел спецификации: Сборочные единицы
      Форматы листов документа: 2xA3
      Примечание: @100~)2xA3
      source file: ..\М10-00.15.000 - Вал.a3d
  - Component [detail]: Электродвигатель / АИР 71B2 IM 3081 IP55 ф."Элком"  | pos. 14  | Масса: 8.3; Раздел спецификации: Прочие изделия; Примечание: См. заказ
  - Component [assembly]: Корпус полипропилен 475 1,1кВт с разъёмной муфтой  | designation М10-00.20.000-PP-475-1,1кВт-M  | pos. 2  | Материал: Полипропилен  ГОСТ 26996-86 (density 900 kg/m3); Масса: 6.15084; Раздел спецификации: Сборочные единицы; Форматы листов документа: 3xA3; Примечание: @100~)3xA3@101~)3xA3
- Part/product: Магна Ins 10-475-3-1,1-PP-Y-E-N-K-0-0-L-0-B-0-X-R  | designation М10-00.00.000-PP-475-1,1кВт-R
    Масса: 15.4162
  - Component [detail]: Заглушка @2~25 FV PPR ф. "FV-Plast"  | qty 4  | pos. 12  | Материал: Полипропилен  ГОСТ 26996-86 (density 900 kg/m3); Масса: 0.0161976; Раздел спецификации: Прочие изделия
  - Component [standard]: Болт М10-6gx60.21.12Х18Н10Т ГОСТ 7798-70  | qty 4  | pos. 8  | Масса: 0.0467; Раздел спецификации: Стандартные изделия; additional columns: М8-6gx55.21.12Х18Н10Т; Сталь 12Х18Н10Т ГОСТ 5632-72
  - Component [standard]: Гайка М10x1,25-6H(S16) ГОСТ 5915-70  | qty 4  | pos. 9  | Масса: 0.01022; Раздел спецификации: Стандартные изделия; Рассекать на разрезах: no; additional columns: М10x1,25-6H (S16); Сталь 12Х18Н10Т ГОСТ 5632-72
  - Component [standard]: Шайба 10 ГОСТ 6402-70  | qty 4  | pos. 10  | Масса: 0.00201; Раздел спецификации: Стандартные изделия; Примечание: Нерж.; Рассекать на разрезах: no; additional columns: 10; Без указания материала
  - Component [standard]: Шайба C.10.21 ГОСТ 11371-78  | qty 4  | pos. 11  | Материал: Сталь 12Х18Н10Т ГОСТ 5632-72 (density 1000 kg/m3); Масса: 0.003438; Раздел спецификации: Стандартные изделия; Рассекать на разрезах: no; additional columns: Сталь 12Х18Н10Т ГОСТ 5632-72
  - Component [standard]: Шайба C.10.21 ГОСТ 11371-78  | qty 4  | pos. 11  | Материал: Сталь 12Х18Н10Т ГОСТ 5632-72 (density 1000 kg/m3); Масса: 0.003438; Раздел спецификации: Стандартные изделия; additional columns: C.8.21; Сталь 12Х18Н10Т ГОСТ 5632-72
  - Component [detail]: Втулка ответная  | designation М10А-00.00.003-01  | pos. 6  | Масса: 0.031838; Раздел спецификации: Детали; Форматы листов документа: A4; Примечание: Заим.; source file: ..\..\..\..\..\..\AquaProf\АкваProf 190\3Д модель\М10А-00.00.003 - Втулка ответная.m3d, ..\М10А-00.00.003-01 - Втулка ответная.cdw
  - Component [detail]: Защитная втулка  | designation М10-00.00.003  | pos. 5  | Масса: 0.0193569; Раздел спецификации: Детали; Форматы листов документа: A4; source file: ..\М10-00.00.003 - Защитная втулка.cdw, ..\М10-00.00.003 - Защитная втулка.m3d
  - Component [detail]: Импеллер Магна10  | designation М10-00.00.001  | pos. 3  | Масса: 0.169927; Раздел спецификации: Детали; Форматы листов документа: A3; source file: ..\М10-00.00.001 - Импеллер Магна10.cdw, ..\М10-00.00.001 - Импеллер Магна10.m3d
  - Component [detail]: Крышка  | designation М10-00.00.002  | pos. 4
      Материал: Полипропилен  ГОСТ 26996-86 (density 900 kg/m3)
      Масса: 0.324102
      Раздел спецификации: Детали
      Форматы листов документа: 4xA4
      Примечание: @100~)4xA4
      source file: ..\М10-00.00.002 - Крышка.cdw, ..\М10-00.00.002 - Крышка.m3d
  - Component [assembly]: Вал  | designation М10-00.15.000-1,1кВт-475  | pos. 1
      Материал: Полипропилен  ГОСТ 26996-86 (density 900 kg/m3)
      Масса: 1.00808
      Раздел спецификации: Сборочные единицы
      Форматы листов документа: 2xA3
      Примечание: @100~)2xA3
      source file: ..\М10-00.15.000 - Вал.a3d
  - Component [detail]: Электродвигатель / АИР 71B2 IM 3081 IP55 ф."Элком"  | pos. 14  | Масса: 8.3; Раздел спецификации: Прочие изделия; Примечание: См. заказ
  - Component [assembly]: Корпус полипропилен 475 1,1кВт  / с резьбовым переходником  | designation М10-00.20.000-PP-475-1,1кВт-R  | pos. 2  | Материал: Полипропилен  ГОСТ 26996-86 (density 900 kg/m3); Масса: 5.23433; Раздел спецификации: Сборочные единицы; Форматы листов документа: 3xA3; Примечание: @100~)3xA3@101~)3xA3
- Part/product: Магна Ins 10-375-3-0,55-PP-Y-V-N-K-0-0-L-0-B-0-X-M  | designation М10-00.00.000-PP-375-0,55кВт-M-Viton
    Масса: 12.2247
  - Component [detail]: Кольцо уплотнительное плоское 10-18-25  | designation Viton  | pos. 13  | Масса: 0.000562973; Раздел спецификации: Прочие изделия
  - Component [assembly]: Корпус полипропилен 375 0,55 кВт  / с разъёмной муфтой  | designation М10-00.20.000-PP-375-0,55кВт-M  | pos. 2
      Материал: Полипропилен  ГОСТ 26996-86 (density 900 kg/m3)
      Масса: 5.91637
      Раздел спецификации: Сборочные единицы
      Форматы листов документа: 3xA3
      Примечание: @100~)3xA3@101~)3xA3
      source file: ..\М10-00.20.000 - Корпус.a3d
  - Component [assembly]: Вал  | designation М10-00.15.000-0,55кВт-375  | pos. 1
      Материал: Полипропилен  ГОСТ 26996-86 (density 900 kg/m3)
      Масса: 0.519317
      Раздел спецификации: Сборочные единицы
      Форматы листов документа: 2xA3
      Примечание: @100~)2xA3
      source file: ..\М10-00.15.000 - Вал.a3d
  - Component [detail]: Крышка  | designation М10-00.00.002  | pos. 4
      Материал: Полипропилен  ГОСТ 26996-86 (density 900 kg/m3)
      Масса: 0.324102
      Раздел спецификации: Детали
      Форматы листов документа: 4xA4
      Примечание: @100~)4xA4
      source file: ..\М10-00.00.002 - Крышка.cdw, ..\М10-00.00.002 - Крышка.m3d
  - Component [detail]: Импеллер Магна10  | designation М10-00.00.001  | pos. 3  | Масса: 0.169927; Раздел спецификации: Детали; Форматы листов документа: A3; source file: ..\М10-00.00.001 - Импеллер Магна10.cdw, ..\М10-00.00.001 - Импеллер Магна10.m3d
  - Component [detail]: Защитная втулка  | designation М10-00.00.003  | pos. 5  | Масса: 0.0193569; Раздел спецификации: Детали; Форматы листов документа: A4; source file: ..\М10-00.00.003 - Защитная втулка.cdw, ..\М10-00.00.003 - Защитная втулка.m3d
  - Component [detail]: Втулка ответная  | designation М10А-00.00.003-01  | pos. 6  | Масса: 0.031838; Раздел спецификации: Детали; Форматы листов документа: A4; Примечание: Заим.; source file: ..\..\..\..\..\..\AquaProf\АкваProf 190\3Д модель\М10А-00.00.003 - Втулка ответная.m3d, ..\М10А-00.00.003-01 - Втулка ответная.cdw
